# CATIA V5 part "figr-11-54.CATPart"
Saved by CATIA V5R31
Part number: Part1
Bounding box of the stored display mesh (mm): x -49.998 to 49.998, y -70 to 70, z 0 to 80.773
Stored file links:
  D:\PROJECTS\Project 2021\US EDITION\CATIA V5 6R 2021\Resources\Part Files\c11_catia_v5_6r2021_prt\figr-11-54.CATPart
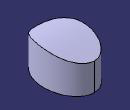
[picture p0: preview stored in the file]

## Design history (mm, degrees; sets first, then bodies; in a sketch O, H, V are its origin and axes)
Set1
  Extrude1: Element1 Sketch2, Lim1 82, Lim2 70, Direction yz-plane
Body1 (main body)
  Sketch1 on xy-plane, origin (0, 0, 0), H (1, 0, 0), V (0, 1, 0)
    ellipse A1 centre (0, 0) semi-axes 70, 50 rotation 90
    point P1 (50, 0)
    coincidence: P1 H, A1 P1
  Pad1: profile Sketch1, direction (0, 0, 1), length 84
  Split1: SplitPlane Extrude1
  Sketch2 on yz-plane, origin (0, 0, 0), H (0, 1, 0), V (0, 0, 1)
    spline S1 through (-90, 50) (-30, 80) (50, 70) (90, 60)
